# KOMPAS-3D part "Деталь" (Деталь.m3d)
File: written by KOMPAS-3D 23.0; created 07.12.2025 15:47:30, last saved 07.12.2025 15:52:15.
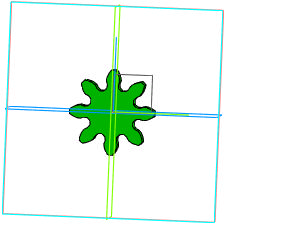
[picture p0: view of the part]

Document properties: Автор: user; Полное имя файла: C:\Users\user\Desktop\Деталь.m3d

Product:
- Part/product: Деталь
    Масса: 0.023899

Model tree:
1. Модель ВиМП
2. Эскиз:2
3. Внеш. контур, ступень 1: Шестерня Z=8, L=16
     Расстояние 2 = 16; Смещение 2 = 16
4. Ось операции:1
5. Внеш. контур, ступень 1: Шестерня Z=8, L=16, средняя плоскость
     Расстояние = 8
6. Точка на монтажном расстоянии
     X = 8; Y = 43; Координата X = 8; Координата Y = 43
7. Внеш. контур, ступень 1: Шестерня Z=8, L=16, ЛСК зубчатого венца  (with: Плоскость XY, Плоскость ZX, Плоскость ZY, Ось X, Ось Y, Ось Z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)
     Ось X. X = 1; Ось Y. Y = 1; Ось Z. Z = 1
8. Точка 1 на оси детали
9. Точка 2 на оси детали
     X = 16; Координата X = 16
10. Ось детали
11. Модель ВиМП (позиционирование)  (with: Модель ВиМП)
